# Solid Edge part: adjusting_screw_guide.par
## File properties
Title: Adjusting screw guide
Author: Robert a Rhodes jr
Template: Normal.par
Last saved by: SOFT
Revision: 26
Application: Solid Edge
Accuracy: 0.99
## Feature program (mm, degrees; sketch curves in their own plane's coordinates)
sketch for "unnamed Protrusion 1" plane through (0, 0, 0) normal (0, -1, 0) x-axis (1, 0, 0)
  circle centre (0, 0) radius 7.9375
extrude "unnamed Protrusion 1" add finite 63.5 along +normal
sketch for "ExtrudedProtrusion_2" plane through (0, -63.5, 0) normal (0, -1, 0) x-axis (1, 0, 0)
  circle centre (0, 0) radius 6.3119
extrude "ExtrudedProtrusion_2" add finite 76.2 along +normal
chamfer "Chamfer_1" setback 1.5748
sketch for "ExtrudedCutout_1" plane through (0, 0, 0) normal (0, 0, 1) x-axis (1, 0, 0)
  line (1.1811, 0) -> (1.1811, -4.7498)
  line (1.1811, -4.7498) -> (-1.1811, -4.7498)
  line (-1.1811, -4.7498) -> (-1.1811, 0)
  line (-1.1811, 0) -> (1.1811, 0)
extrude "ExtrudedCutout_1" cut finite 101.6 symmetric
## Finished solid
Body 1: solid body, 10 faces, 16 edges, 8 vertices.
  Faces by surface: plane 7, cylinder 2, cone 1
  Edges by curve: circle 8, line 8
Bounding box of the edges (mm): 15.875 x 139.700 x 15.875, from (-7.9375, -139.7, -7.9375) to (7.9375, 0, 7.9375).
Cylindrical faces by radius (mm): R6.3119 x1, R7.9375 x1
Conical faces (half-angle, radius in mm at the cone's reference point): 45 deg R6.3119 x1
Planar faces by outward normal: +x 1, +y 3, -x 1, -y 2
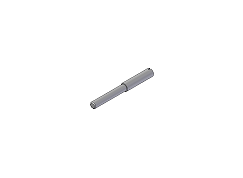
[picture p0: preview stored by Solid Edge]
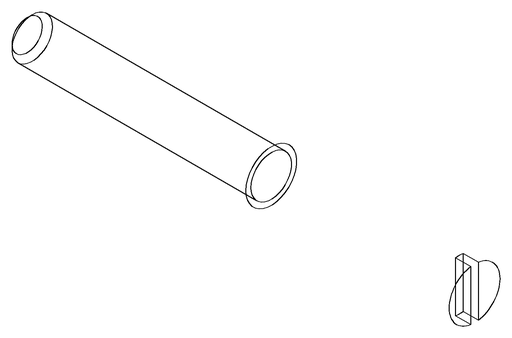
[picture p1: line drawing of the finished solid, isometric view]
